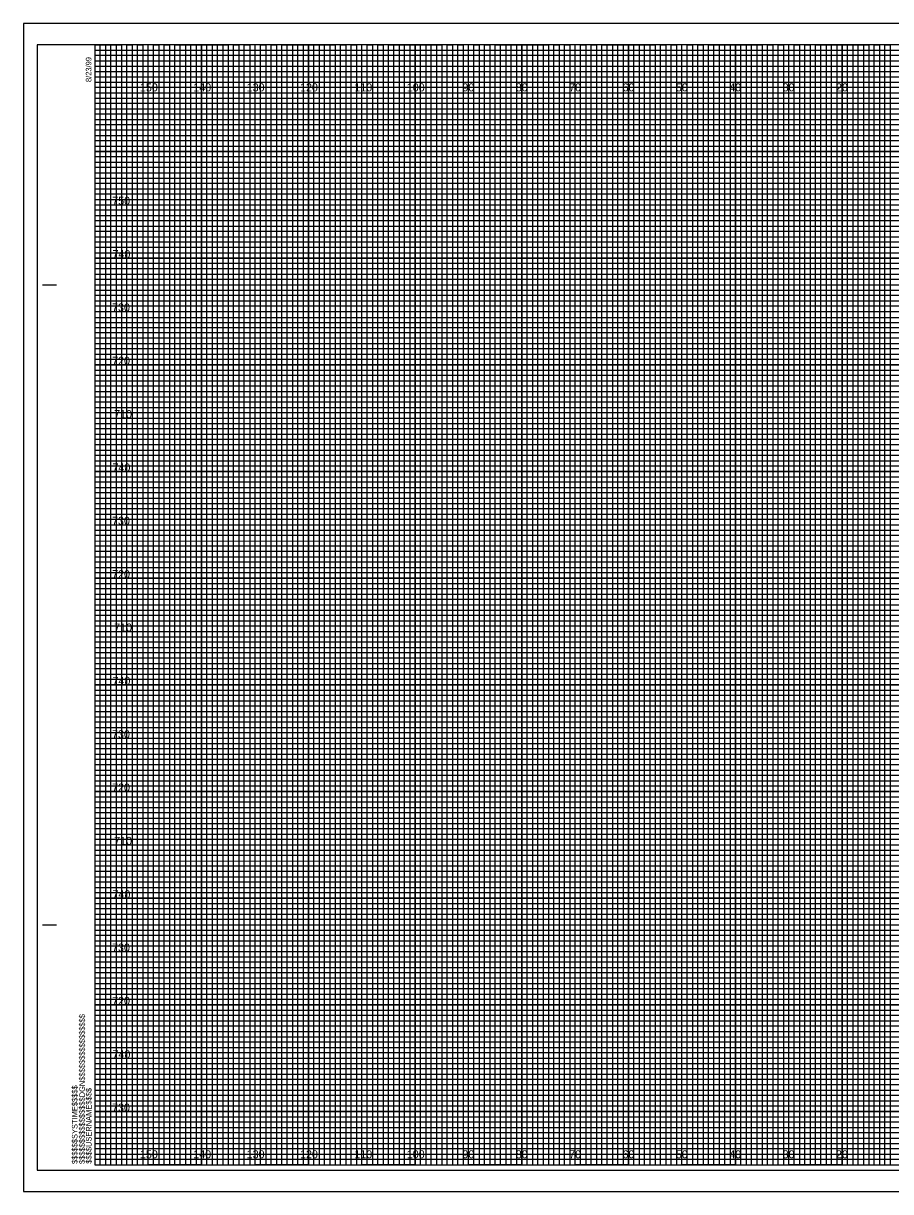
# Model space of a CAD drawing. Extents: x -13 to 323, y -5 to 214.
# Drawn here: x -13.4 to 149.1, y -5 to 214 of the extents above; entities that cross this region are included whole.
import ezdxf

# ---------------------------------------------------------------- set-up
doc = ezdxf.new("R2010")
doc.units = 0
for name, color, linetype in [('Exist Cross Section Cell', 7, 'Continuous'), ('Exist XS Center Line Elevation Label', 7, 'Continuous'), ('Exist XS Ground Line', 7, 'Continuous'), ('Prop XS Ditch Slope Text', 7, 'Continuous'), ('Prop XS Ditch Standard Text', 7, 'Continuous'), ('Prop XS Dump Level', 7, 'Continuous'), ('Prop XS Finish Grade', 7, 'Continuous'), ('Prop XS Finish Grade Earthwork', 7, 'Continuous'), ('Prop XS SE Text', 7, 'Continuous'), ('Prop XS Side Slope Text', 7, 'Continuous'), ('Prop XS Subgrade Earthwork', 7, 'Continuous')]:
    doc.layers.add(name, color=color, linetype=linetype)

msp = doc.modelspace()

# ---------------------------------------------------------------- linework, layer by layer
at = {"layer": 'Exist XS Center Line Elevation Label'}
for points in [[(0, 210), (5, 210), (5, 0), (15, 0), (15, 210), (25, 210), (25, 0), (35, 0), (35, 210), (45, 210), (45, 0), (55, 0), (55, 210), (65, 210), (65, 0), (75, 0), (75, 210), (85, 210), (85, 0), (95, 0), (95, 210), (105, 210), (105, 0), (115, 0), (115, 210), (125, 210), (125, 0), (135, 0), (135, 210), (145, 210), (145, 0), (155, 0)], [(0, 205), (275, 205)], [(0, 185), (320, 185), (320, 195), (0, 195)], [(0, 165), (320, 165), (320, 175), (0, 175)], [(0, 145), (320, 145), (320, 155), (0, 155)], [(0, 125), (320, 125), (320, 135), (0, 135)], [(0, 105), (320, 105), (320, 115), (0, 115)], [(0, 85), (320, 85), (320, 95), (0, 95)], [(0, 65), (320, 65), (320, 75), (0, 75)], [(0, 45), (320, 45), (320, 55), (0, 55)], [(0, 25), (320, 25), (320, 35), (0, 35)], [(0, 5), (320, 5), (320, 15), (0, 15)]]:
    msp.add_lwpolyline(points, dxfattribs=at)
at = {"layer": 'Exist XS Ground Line'}
for p, q in [((10, 210), (0, 210)), ((10, 0), (10, 210)), ((30, 210), (20, 210)), ((20, 210), (20, 0)), ((30, 0), (30, 210)), ((50, 210), (40, 210)), ((40, 210), (40, 0)), ((50, 0), (50, 210)), ((70, 210), (60, 210)), ((60, 210), (60, 0)), ((70, 0), (70, 210)), ((90, 210), (80, 210)), ((80, 210), (80, 0)), ((90, 0), (90, 210)), ((110, 210), (100, 210)), ((100, 210), (100, 0)), ((110, 0), (110, 210)), ((130, 210), (120, 210)), ((120, 210), (120, 0)), ((130, 0), (130, 210)), ((150, 210), (140, 210)), ((140, 210), (140, 0)), ((20, 0), (10, 0)), ((40, 0), (30, 0)), ((60, 0), (50, 0)), ((80, 0), (70, 0)), ((100, 0), (90, 0)), ((120, 0), (110, 0)), ((140, 0), (130, 0))]:
    msp.add_line(p, q, dxfattribs=at)
for points in [[(0, 200), (320, 200), (320, 190), (0, 190)], [(0, 180), (320, 180), (320, 170), (0, 170)], [(0, 160), (320, 160), (320, 150), (0, 150)], [(0, 140), (320, 140), (320, 130), (0, 130)], [(0, 120), (320, 120), (320, 110), (0, 110)], [(0, 100), (320, 100), (320, 90), (0, 90)], [(0, 80), (320, 80), (320, 70), (0, 70)], [(0, 60), (320, 60), (320, 50), (0, 50)], [(0, 40), (320, 40), (320, 30), (0, 30)], [(0, 20), (320, 20), (320, 10), (0, 10)]]:
    msp.add_lwpolyline(points, dxfattribs=at)
at = {"layer": 'Prop XS Ditch Slope Text'}
msp.add_lwpolyline([(-10.8, -1), (322.4, -1), (322.4, 210), (-10.8, 210)], close=True, dxfattribs=at)
at = {"layer": 'Prop XS Ditch Standard Text'}
msp.add_lwpolyline([(-13.4, -5), (323.3, -5), (323.3, 214), (-13.4, 214)], close=True, dxfattribs=at)
at = {"layer": 'Prop XS Dump Level'}
for p, q in [((-9.8, 165), (-7.3, 165)), ((-9.7, 165), (-7.2, 165)), ((-9.8, 45), (-7.3, 45)), ((-9.7, 45), (-7.2, 45)), ((0, 0), (0, 0)), ((0, 0), (0, 0)), ((0, 0), (0, 0)), ((0, 0), (0, 0)), ((0, 0), (0, 0)), ((0, 0), (0, 0)), ((0, 0), (0, 0))]:
    msp.add_line(p, q, dxfattribs=at)
msp.add_lwpolyline([(320, 210), (0, 210), (0, 0), (320, 0)], close=True, dxfattribs=at)
at = {"layer": 'Prop XS Finish Grade Earthwork'}
for p, q in [((10, 0), (10, 210)), ((20, 0), (20, 210)), ((30, 0), (30, 210)), ((40, 0), (40, 210)), ((50, 0), (50, 210)), ((60, 0), (60, 210)), ((70, 0), (70, 210)), ((80, 0), (80, 210)), ((90, 0), (90, 210)), ((100, 0), (100, 210)), ((110, 0), (110, 210)), ((120, 0), (120, 210)), ((130, 0), (130, 210)), ((140, 0), (140, 210)), ((0, 200), (320, 200)), ((0, 190), (320, 190)), ((0, 180), (320, 180)), ((0, 170), (320, 170)), ((0, 160), (320, 160)), ((0, 150), (320, 150)), ((0, 140), (320, 140)), ((0, 130), (320, 130)), ((0, 120), (320, 120)), ((0, 110), (320, 110)), ((0, 100), (320, 100)), ((0, 90), (320, 90)), ((0, 80), (320, 80)), ((0, 70), (320, 70)), ((0, 60), (320, 60)), ((0, 50), (320, 50)), ((0, 40), (320, 40)), ((0, 30), (320, 30)), ((0, 20), (320, 20)), ((0, 10), (320, 10))]:
    msp.add_line(p, q, dxfattribs=at)
at = {"layer": 'Prop XS SE Text'}
for p, q in [((0, 209), (260, 209)), ((260, 207.98), (0, 207.98)), ((0, 207.98), (0, 207)), ((0, 207), (260, 207)), ((260, 205.89), (0, 205.89)), ((0, 205.89), (0, 204)), ((0, 204), (320, 204))]:
    msp.add_line(p, q, dxfattribs=at)
for points in [[(0, 203), (270, 203), (320, 203), (320, 202), (0, 202)], [(0, 201), (320, 201), (320, 199), (0, 199)], [(0, 198), (320, 198), (320, 197), (0, 196.98)], [(0, 196), (320, 196), (320, 194), (0, 194)], [(0, 193), (320, 193), (320, 192), (0, 192)], [(0, 191), (320, 191), (320, 189), (0, 189)], [(0, 188), (320, 188), (320, 187), (0, 187)], [(0, 186), (320, 186), (320, 184), (0, 184)], [(0, 183), (320, 183), (320, 182), (0, 182)], [(0, 181), (320, 181), (320, 179), (0, 179)], [(0, 178), (320, 178), (320, 177), (0, 177)], [(0, 176), (320, 176), (320, 173.95), (320, 173), (320, 172), (0, 172)], [(0, 174), (320, 174), (320, 173), (0, 173)], [(0, 171), (320, 171), (320, 169), (0, 169.03)], [(0, 169.03), (320, 169), (320, 168), (0, 168)], [(0, 167), (320, 167), (320, 166), (0, 166)], [(0, 164), (320, 164), (320, 163), (0, 163)], [(0, 162), (320, 162), (320, 161), (0, 161)], [(-0.07, 158.89), (320, 158.89), (320, 157.88), (-0.07, 157.88)], [(0, 157), (320, 157), (320, 156), (0, 156)], [(0, 154), (320, 154), (320, 153), (0, 153)], [(0, 152), (320, 152), (320, 151), (0, 151)], [(0, 149), (320, 149), (320, 148), (0, 148)], [(0, 147), (320, 147), (320, 146), (0, 146)], [(0, 144), (320, 144), (320, 143), (0, 143)], [(0, 142), (320, 142), (320, 141), (0, 141)], [(0, 139), (320, 139), (319.99, 137.98), (0, 138)], [(0, 137), (320, 137), (320, 136), (0, 136)], [(0, 134), (320, 134), (320, 133), (0, 133)], [(0, 132), (320, 132), (320, 131), (0, 131)], [(0, 129), (320, 129), (320, 128), (0, 128)], [(0, 127), (320, 127), (320, 126), (0, 126)], [(0, 124), (320, 124), (320, 123), (0, 123)], [(0, 122), (320, 122), (320, 121), (0, 121)], [(0, 119), (320, 119), (320, 118), (0, 118)], [(0, 116.99), (320.07, 116.91), (320, 116), (0, 116)], [(0, 114), (320, 114), (320, 113), (0, 113)], [(0, 112), (320, 112), (320, 111), (0, 111)], [(0, 109), (320, 109), (320, 108), (0, 108)], [(0, 107), (320, 107), (320, 106), (0, 106)], [(0, 104), (320, 104), (320, 103), (0, 103)], [(0, 102), (320, 102), (320, 101), (0, 101)], [(0, 99), (320, 99), (320, 98), (0, 98)], [(0, 97), (320, 97), (320, 96), (0, 96)], [(0, 94), (320, 94), (320, 93), (0, 93)], [(0, 92), (320, 92), (320, 91), (0, 91)], [(0, 89), (320, 89), (320, 88), (0, 88)], [(0, 87), (320, 87), (320, 86), (0, 86)], [(0, 84), (320, 84), (320, 83), (0, 83)], [(0, 82), (320, 82), (320, 81), (0, 81)], [(0, 79), (320, 79), (319.99, 77.98), (0, 78)], [(0, 77), (320, 77), (320, 76), (0, 76)], [(0, 74), (320, 74), (320, 73), (0, 73)], [(0, 72), (320, 72), (320, 71), (0, 71)], [(0, 69), (320, 69), (320, 68), (0, 68)], [(0, 67), (320, 67), (320, 66), (0, 66)], [(0, 64), (320, 64), (320, 63), (0, 63)], [(0, 62), (320, 62), (320, 61), (0, 61)], [(0, 59), (320, 59), (320, 58), (0, 58)], [(0, 56.99), (320.07, 56.91), (320, 56), (0, 56)], [(0, 54), (320, 54), (320, 53), (0, 53)], [(0, 52), (320, 52), (320, 51), (0, 51)], [(0, 49), (320, 49), (320, 48), (0, 48)], [(0, 47), (320, 47), (320, 46), (0, 46)], [(0, 44), (320, 44), (320, 43), (0, 43)], [(0, 42), (320, 42), (320, 41), (0, 41)], [(0, 39), (320, 39), (320, 38), (0, 38)], [(0, 37), (320, 37), (320, 36), (0, 36)], [(0, 34), (320, 34), (320, 33), (0, 33)], [(0, 32), (320, 32), (320, 31), (0, 31)], [(0, 29), (320, 29), (320, 28), (0, 28)], [(0, 27), (320, 27), (320, 26), (0, 26)], [(0, 24), (320, 24), (320, 23), (0, 23)], [(0, 22), (320, 22), (320, 21), (0, 21)], [(0, 19), (320, 19), (320, 18), (0, 18)], [(0, 17), (320, 17), (320, 16), (0, 16)], [(0, 14), (320, 14), (320, 13), (0, 13)], [(0, 12), (320, 12), (320, 11), (0, 11)], [(0, 9), (320, 9), (320, 8), (0, 8)], [(0, 7), (320, 7), (320, 6), (0, 6)], [(0, 4), (320, 4), (320, 3), (0, 3)], [(0, 2), (320, 2), (320, 1), (0, 1)]]:
    msp.add_lwpolyline(points, dxfattribs=at)
at = {"layer": 'Prop XS Side Slope Text'}
for points in [[(0, 0), (1, 0), (1, 210), (2, 210), (2, 0)], [(2, 0), (3, 0), (3, 210), (4, 210), (4, 0)], [(5, 0), (6, 0), (6, 210), (7, 210), (7, 0)], [(7, 0), (8, 0), (8, 210), (9, 210), (9, 0)], [(10, 0), (11, 0), (11, 210), (12, 210), (12, 0)], [(12, 0), (13, 0), (13, 210), (14, 210), (14, 0)], [(15, 0), (16, 0), (16, 210), (17, 210), (17, 0)], [(17, 0), (18, 0), (18, 210), (19, 210), (19, 0)], [(20, 0), (21, 0), (21, 210), (22, 210), (22, 0)], [(22, 0), (23, 0), (23, 210), (24, 210), (24, 0)], [(25, 0), (26, 0), (26, 210), (27, 210), (27, 0)], [(27, 0), (28, 0), (28, 210), (29, 210), (29, 0)], [(30, 0), (31, 0), (31, 210), (32, 210), (32, 0)], [(32, 0), (33, 0), (33, 210), (34, 210), (34, 0)], [(35, 0), (36, 0), (36, 210), (37, 210), (37, 0)], [(37, 0), (38, 0), (38, 210), (39, 210), (39, 0)], [(40, 0), (41, 0), (41, 210), (42, 210), (42, 0)], [(42, 0), (43, 0), (43, 210), (44, 210), (44, 0)], [(45, 0), (46, 0), (46, 210), (47, 210), (47, 0)], [(47, 0), (48, 0), (48, 210), (49, 210), (49, 0)], [(50, 0), (51, 0), (51, 210), (52, 210), (52, 0)], [(52, 0), (53, 0), (53, 210), (54, 210), (54, 0)], [(55, 0), (56, 0), (56, 210), (57, 210), (57, 0)], [(57, 0), (58, 0), (58, 210), (59, 210), (59, 0)], [(60, 0), (61, 0), (61, 210), (62, 210), (62, 0)], [(62, 0), (63, 0), (63, 210), (64, 210), (64, 0)], [(65, 0), (66, 0), (66, 210), (67, 210), (67, 0)], [(67, 0), (68, 0), (68, 210), (69, 210), (69, 0)], [(70, 0), (71, 0), (71, 210), (72, 210), (72, 0)], [(72, 0), (73, 0), (73, 210), (74, 210), (74, 0)], [(75, 0), (76, 0), (76, 210), (77, 210), (77, 0)], [(77, 0), (78, 0), (78, 210), (79, 210), (79, 0)], [(80, 0), (81, 0), (81, 210), (82, 210), (82, 0)], [(82, 0), (83, 0), (83, 210), (84, 210), (84, 0)], [(85, 0), (86, 0), (86, 210), (87, 210), (87, 0)], [(87, 0), (88, 0), (88, 210), (89, 210), (89, 0)], [(90, 0), (91, 0), (91, 210), (92, 210), (92, 0)], [(92, 0), (93, 0), (93, 210), (94, 210), (94, 0)], [(95, 0), (96, 0), (96, 210), (97, 210), (97, 0)], [(97, 0), (98, 0), (98, 210), (99, 210), (99, 0)], [(100, 0), (101, 0), (101, 210), (102, 210), (102, 0)], [(102, 0), (103, 0), (103, 210), (104, 210), (104, 0)], [(105, 0), (106, 0), (106, 210), (107, 210), (107, 0)], [(107, 0), (108, 0), (108, 210), (109, 210), (109, 0)], [(110, 0), (111, 0), (111, 210), (112, 210), (112, 0)], [(112, 0), (113, 0), (113, 210), (114, 210), (114, 0)], [(115, 0), (116, 0), (116, 210), (117, 210), (117, 0)], [(117, 0), (118, 0), (118, 210), (119, 210), (119, 0)], [(120, 0), (121, 0), (121, 210), (122, 210), (122, 0)], [(122, 0), (123, 0), (123, 210), (124, 210), (124, 0)], [(125, 0), (126, 0), (126, 210), (127, 210), (127, 0)], [(127, 0), (128, 0), (128, 210), (129, 210), (129, 0)], [(130, 0), (131, 0), (131, 210), (132, 210), (132, 0)], [(132, 0), (133, 0), (133, 210), (134, 210), (134, 0)], [(135, 0), (136, 0), (136, 210), (137, 210), (137, 0)], [(137, 0), (138, 0), (138, 210), (139, 210), (139, 0)], [(140, 0), (141, 0), (141, 210), (142, 210), (142, 0)], [(142, 0), (143, 0), (143, 210), (144, 210), (144, 0)], [(145, 0), (146, 0), (146, 210), (147, 210), (147, 0)], [(147, 0), (148, 0), (148, 210), (149, 210), (149, 0)]]:
    msp.add_lwpolyline(points, dxfattribs=at)
at = {"layer": 'Prop XS Subgrade Earthwork'}
for p, q in [((323.3, 214), (-13.4, 214)), ((-13.4, 214), (-13.4, -5)), ((-13.4, -5), (323.3, -5))]:
    msp.add_line(p, q, dxfattribs=at)

# ---------------------------------------------------------------- texts
at = {"layer": 'Exist Cross Section Cell'}
for s, p in [('150', (8.44, 201.25)), ('140', (18.44, 201.25)), ('130', (28.44, 201.25)), ('120', (38.44, 201.25)), ('110', (48.62, 201.25)), ('100', (58.44, 201.25)), ('90', (68.86, 201.25)), ('80', (78.86, 201.25)), ('70', (88.86, 201.25)), ('60', (98.86, 201.25)), ('50', (108.86, 201.25)), ('40', (118.86, 201.25)), ('30', (128.86, 201.25)), ('20', (138.86, 201.25)), ('150', (8.44, 1.25)), ('140', (18.44, 1.25)), ('130', (28.44, 1.25)), ('120', (38.44, 1.25)), ('110', (48.62, 1.25)), ('100', (58.44, 1.25)), ('90', (68.86, 1.25)), ('80', (78.86, 1.25)), ('70', (88.86, 1.25)), ('60', (98.86, 1.25)), ('50', (108.86, 1.25)), ('40', (118.86, 1.25)), ('30', (128.86, 1.25)), ('20', (138.86, 1.25))]:
    msp.add_text(s, height=1.5, dxfattribs=at).set_placement(p)
at = {"layer": 'Prop XS Dump Level'}
for s, p in [('8/23/99', (-0.65, 203)), ('$$$$$$$$$$$$$$$$DGN$$$$$$$$$$$$$$$$', (-1.88, 0.18)), ('$$$$$$SYSTIME$$$$$', (-3.26, 0.18)), ('$$$$USERNAME$$$$', (-0.62, 0.23))]:
    msp.add_text(s, height=1.05, rotation=90, dxfattribs=at).set_placement(p)
at = {"layer": 'Prop XS Finish Grade'}
for s, p in [('750', (3.25, 180)), ('740', (3.3, 170)), ('730', (3.22, 160)), ('720', (3.23, 150)), ('710', (3.61, 140)), ('740', (3.3, 130)), ('730', (3.22, 120)), ('720', (3.23, 110)), ('710', (3.61, 100)), ('740', (3.3, 90)), ('730', (3.22, 80)), ('720', (3.23, 70)), ('710', (3.61, 60)), ('740', (3.3, 50)), ('730', (3.22, 40)), ('720', (3.23, 30)), ('740', (3.3, 20)), ('730', (3.22, 10))]:
    msp.add_text(s, height=1.5, dxfattribs=at).set_placement(p)

doc.saveas('drawing.dxf')
